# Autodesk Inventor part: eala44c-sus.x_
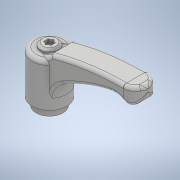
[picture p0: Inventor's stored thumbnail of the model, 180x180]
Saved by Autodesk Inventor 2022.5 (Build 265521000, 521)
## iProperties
Created: 2018-05
Part Number: eala44c-sus.x_
Material: 一般
Document SubType Name: Modeling
Designer: imaocorp
Density: 1 g/cm^3
Appearance: 既定
Sending System: SOLIDWORKS 2016-2016286
MC: AMD64
MC_MODEL: AMD64 Family 21 Model 2 Stepping 0, AuthenticAMD
OS: Windows_NT
FRU: Parasolid Version 28.0, build 224,  7-29-2016
FORMAT: text
GUISE: transmit
KEY: eala44c-sus
FILE: eala44c-sus.x_t
DATE: Fri May 18 11:28:41 2018
Author: imaocorp
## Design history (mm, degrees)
feature "Base1"
node "ソリッド1"
